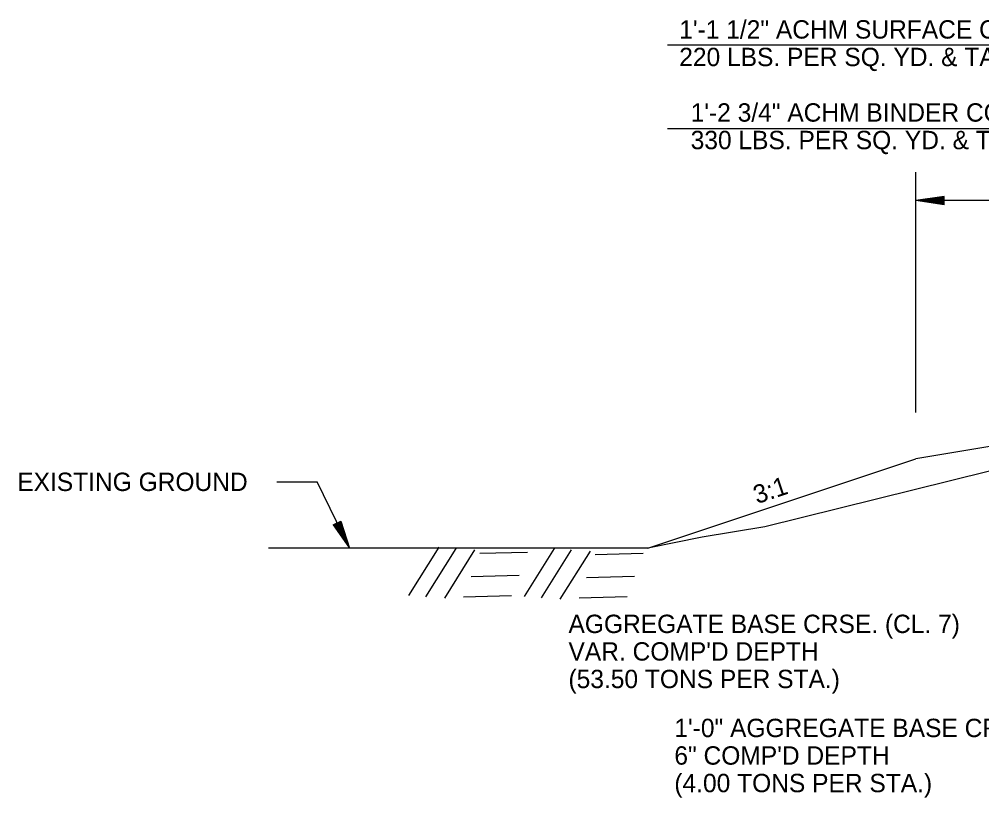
# Model space of a CAD drawing. Extents: x 6848689 to 6848907, y 1900908 to 1901005.
# Drawn here: x 6848689.34 to 6848723.43, y 1900914.44 to 1900942 of the extents above; entities that cross this region are included whole.
import ezdxf

# ---------------------------------------------------------------- set-up
doc = ezdxf.new("R2010")
doc.units = 0
for name, color, linetype in [('Default', 7, 'Continuous'), ('R_Draft', 7, 'Continuous'), ('R_No Plot', 7, 'Continuous')]:
    doc.layers.add(name, color=color, linetype=linetype)

msp = doc.modelspace()

# ---------------------------------------------------------------- linework, layer by layer
at = {"layer": 'Default'}
for p, q in [((6848731.103, 1900928.102), (6848721.097, 1900926.435)), ((6848711.61, 1900923.272), (6848721.097, 1900926.435)), ((6848711.61, 1900923.272), (6848698.176, 1900923.272))]:
    msp.add_line(p, q, dxfattribs=at)
msp.add_lwpolyline([(6848726.329, 1900926.648), (6848715.752, 1900924.027), (6848713.532, 1900923.659), (6848711.61, 1900923.272)], dxfattribs=at)
at = {"layer": 'R_Draft'}
for p, q in [((6848722.097, 1900935.727), (6848721.097, 1900935.577)), ((6848722.097, 1900935.427), (6848721.097, 1900935.577)), ((6848722.097, 1900935.702), (6848721.264, 1900935.577)), ((6848722.097, 1900935.452), (6848721.264, 1900935.577)), ((6848722.097, 1900935.677), (6848721.436, 1900935.577)), ((6848722.097, 1900935.478), (6848721.436, 1900935.577)), ((6848722.097, 1900935.652), (6848721.603, 1900935.577)), ((6848722.097, 1900935.503), (6848721.603, 1900935.577)), ((6848722.097, 1900935.626), (6848721.772, 1900935.577)), ((6848722.097, 1900935.529), (6848721.772, 1900935.577)), ((6848722.097, 1900935.601), (6848721.939, 1900935.577)), ((6848722.097, 1900935.554), (6848721.939, 1900935.577)), ((6848722.097, 1900935.427), (6848722.097, 1900935.727)), ((6848698.468, 1900925.617), (6848699.891, 1900925.617)), ((6848700.464, 1900924.105), (6848700.733, 1900924.236)), ((6848700.464, 1900924.105), (6848701.038, 1900923.272)), ((6848700.486, 1900924.116), (6848700.965, 1900923.422)), ((6848700.509, 1900924.127), (6848700.889, 1900923.577)), ((6848700.532, 1900924.138), (6848700.816, 1900923.726)), ((6848700.555, 1900924.149), (6848700.742, 1900923.879)), ((6848700.578, 1900924.16), (6848700.668, 1900924.029)), ((6848700.62, 1900924.181), (6848700.668, 1900924.029)), ((6848700.643, 1900924.192), (6848700.742, 1900923.879)), ((6848700.666, 1900924.203), (6848700.816, 1900923.726)), ((6848700.688, 1900924.214), (6848700.889, 1900923.577)), ((6848700.711, 1900924.225), (6848700.965, 1900923.422)), ((6848700.733, 1900924.236), (6848701.038, 1900923.272))]:
    msp.add_line(p, q, dxfattribs=at)
at = {"layer": 'R_No Plot'}
for p, q in [((6848736.124, 1900941.082), (6848712.301, 1900941.082)), ((6848736.124, 1900938.117), (6848712.301, 1900938.117)), ((6848721.095, 1900928.081), (6848721.095, 1900936.581)), ((6848735.099, 1900935.577), (6848721.097, 1900935.577)), ((6848701.038, 1900923.272), (6848699.891, 1900925.617)), ((6848703.145, 1900921.599), (6848704.212, 1900923.306)), ((6848703.745, 1900921.55), (6848704.812, 1900923.258)), ((6848707.237, 1900921.561), (6848708.304, 1900923.268)), ((6848704.414, 1900921.504), (6848705.482, 1900923.211)), ((6848705.653, 1900923.092), (6848707.349, 1900923.138)), ((6848707.837, 1900921.512), (6848708.904, 1900923.22)), ((6848708.506, 1900921.466), (6848709.574, 1900923.173)), ((6848709.745, 1900923.054), (6848711.441, 1900923.1)), ((6848705.347, 1900922.274), (6848707.043, 1900922.32)), ((6848709.439, 1900922.236), (6848711.135, 1900922.281)), ((6848705.08, 1900921.555), (6848706.776, 1900921.6)), ((6848709.172, 1900921.517), (6848710.868, 1900921.562))]:
    msp.add_line(p, q, dxfattribs=at)

# ---------------------------------------------------------------- texts
at = {"layer": 'R_Draft'}
for s, p in [('1\'-1 1/2" ACHM SURFACE COURSE (1/2")', (6848712.718, 1900941.313)), ('220 LBS. PER SQ. YD. & TACK COAT', (6848712.718, 1900940.338)), ('1\'-2 3/4" ACHM BINDER COURSE (1")', (6848713.123, 1900938.373)), ('330 LBS. PER SQ. YD. & TACK COAT', (6848713.123, 1900937.398)), ('EXISTING GROUND', (6848689.274, 1900925.298)), ('AGGREGATE BASE CRSE. (CL. 7)', (6848708.795, 1900920.27)), ("VAR. COMP'D DEPTH", (6848708.795, 1900919.295)), ('(53.50 TONS PER STA.)', (6848708.795, 1900918.32)), ('1\'-0" AGGREGATE BASE CRSE. (CL. 7)', (6848712.545, 1900916.586)), ('6" COMP\'D DEPTH', (6848712.545, 1900915.611)), ('(4.00 TONS PER STA.)', (6848712.545, 1900914.636))]:
    msp.add_text(s, height=0.65, dxfattribs=at).set_placement(p)
msp.add_text('3:1', height=0.65, rotation=18.435, dxfattribs=at).set_placement((6848715.471, 1900924.832))

doc.saveas('drawing.dxf')
